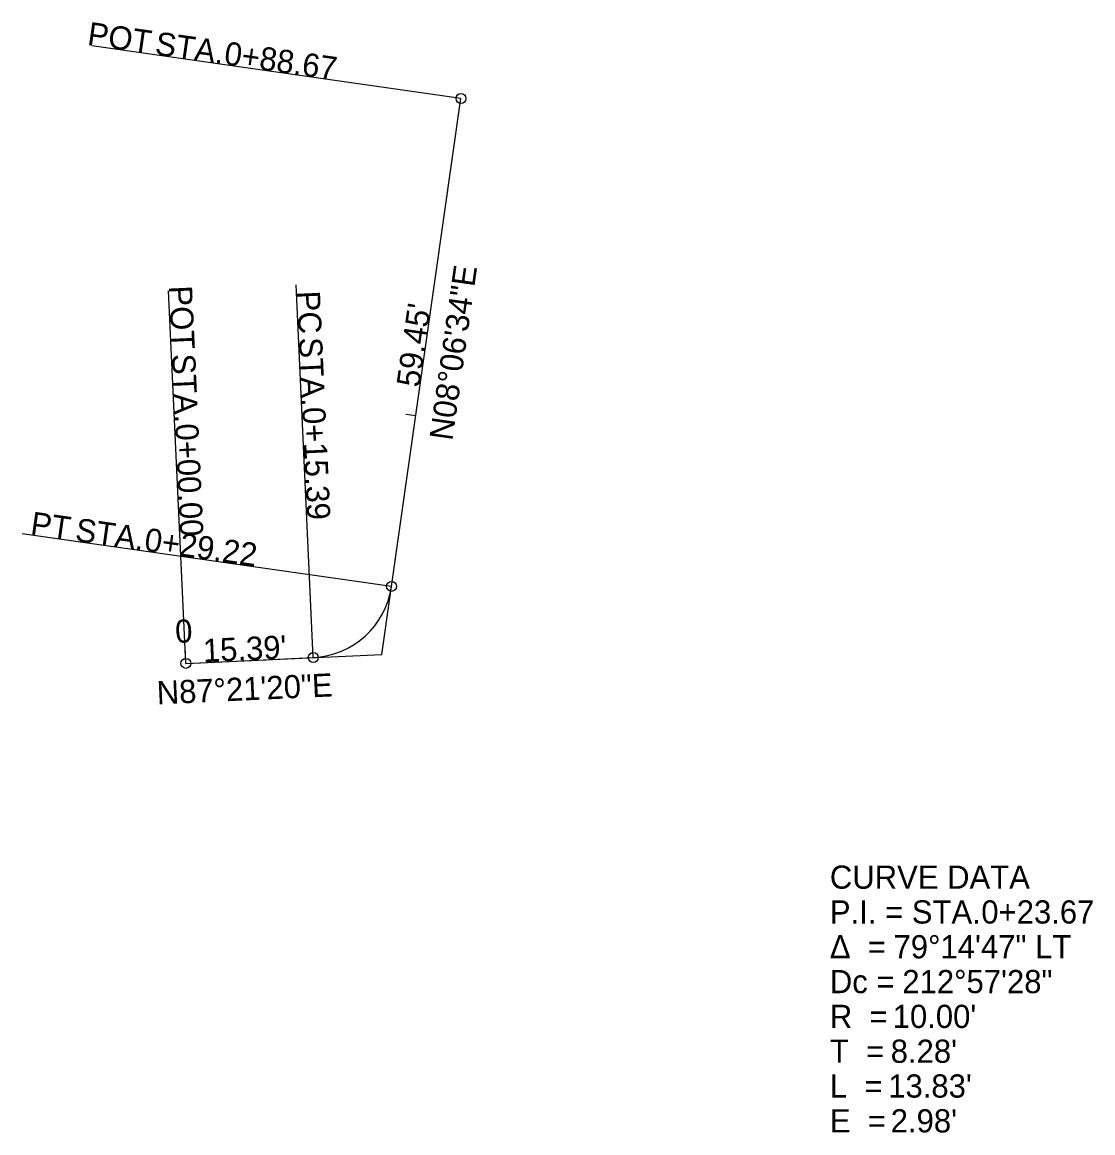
# Model space of a CAD drawing. Extents: x 2047518 to 2047647, y 284910 to 285044.
import ezdxf

# ---------------------------------------------------------------- set-up
doc = ezdxf.new("R2010")
doc.units = 0
for name, color, linetype in [('_CIVIL_CONSTRUCTION', 7, 'Continuous'), ('PF_P_Sta_Elev_Text', 7, 'Continuous'), ('PF_P_Text_Strip_Grades_20', 7, 'Continuous'), ('PF_X_Text_Strip_Grade', 7, 'Continuous'), ('RW_X_CL_100_Distances', 7, 'Continuous'), ('RW_X_Esmt_SH', 7, 'Continuous'), ('SH_Major_Grid_Line', 7, 'Continuous')]:
    doc.layers.add(name, color=color, linetype=linetype)

msp = doc.modelspace()

# ---------------------------------------------------------------- linework, layer by layer
at = {"layer": '_CIVIL_CONSTRUCTION'}
for p, q in [((2047561.59, 284967.64), (2047571.14, 285034.7)), ((2047537.95, 284966.55), (2047561.59, 284967.64))]:
    msp.add_line(p, q, dxfattribs=at)
msp.add_arc((2047552.86, 284977.25), 10, 272.6444, 351.8907, dxfattribs=at)
at = {"layer": 'PF_P_Text_Strip_Grades_20'}
for p, q in [((2047565.69, 284996.41), (2047564.5, 284996.58)), ((2047537.95, 284966.55), (2047537.85, 284968.55))]:
    msp.add_line(p, q, dxfattribs=at)
at = {"layer": 'RW_X_CL_100_Distances'}
for p, q in [((2047562.76, 284975.84), (2047571.14, 285034.7)), ((2047537.95, 284966.55), (2047553.32, 284967.26))]:
    msp.add_line(p, q, dxfattribs=at)
msp.add_arc((2047552.86, 284977.25), 10, 272.6444, 351.8907, dxfattribs=at)
at = {"layer": 'RW_X_Esmt_SH'}
for p, q in [((2047562.76, 284975.84), (2047571.14, 285034.7)), ((2047537.95, 284966.55), (2047553.32, 284967.26))]:
    msp.add_line(p, q, dxfattribs=at)
msp.add_arc((2047552.86, 284977.25), 10, 272.6444, 351.8907, dxfattribs=at)
at = {"layer": 'SH_Major_Grid_Line'}
for p, q in [((2047571.14, 285034.7), (2047526.59, 285041.05)), ((2047537.95, 284966.55), (2047535.87, 285011.5)), ((2047553.32, 284967.26), (2047551.24, 285012.21)), ((2047562.76, 284975.84), (2047518.21, 284982.19))]:
    msp.add_line(p, q, dxfattribs=at)
for centre in [(2047571.14, 285034.7), (2047562.76, 284975.84), (2047537.95, 284966.55), (2047553.32, 284967.26)]:
    msp.add_circle(centre, 0.6, dxfattribs=at)

# ---------------------------------------------------------------- texts
at = {"layer": '_CIVIL_CONSTRUCTION'}
for s, rotation, p in [('N08°06\'34"E', 81.8907, (2047570.1, 284993.34)), ('N87°21\'20"E', 2.6444, (2047534.5, 284961.59))]:
    msp.add_text(s, height=2.8, rotation=rotation, dxfattribs=at).set_placement(p)
at = {"layer": 'PF_P_Sta_Elev_Text'}
for s, p in [('CURVE DATA', (2047615.64, 284939.36)), ('P.I. = STA. ', (2047615.64, 284935.16)), ('0+23.67', (2047633.91, 284935.16)), ('Δ  = ', (2047615.64, 284930.96)), ('79°14\'47" LT', (2047623.32, 284930.96)), ('Dc = ', (2047615.64, 284926.76)), ('212°57\'28"', (2047624.38, 284926.76)), ('R  = ', (2047615.64, 284922.56)), ("10.00'", (2047623.22, 284922.56)), ('T  = ', (2047615.64, 284918.36)), ("8.28'", (2047622.98, 284918.36)), ('L  = ', (2047615.64, 284914.16)), ("13.83'", (2047622.68, 284914.16)), ('E  = ', (2047615.64, 284909.96)), ("2.98'", (2047622.98, 284909.96))]:
    msp.add_text(s, height=2.8, dxfattribs=at).set_placement(p)
at = {"layer": 'PF_P_Text_Strip_Grades_20'}
msp.add_text('0', height=2.8, rotation=2.6444, dxfattribs=at).set_placement((2047536.72, 284969))
at = {"layer": 'PF_X_Text_Strip_Grade'}
for s, rotation, p in [("59.45'", 81.8907, (2047566.12, 284999.77)), ("15.39'", 2.6444, (2047540.07, 284966.69))]:
    msp.add_text(s, height=2.8, rotation=rotation, dxfattribs=at).set_placement(p)
at = {"layer": 'SH_Major_Grid_Line'}
for s, rotation, p in [('POT', 351.8907, (2047525.97, 285041.18)), (' STA. ', 351.8907, (2047533.1, 285040.16)), ('0+88.67', 351.8907, (2047542.46, 285038.83)), ('POT', 272.6444, (2047535.89, 285012.07)), ('PC', 272.6444, (2047551.32, 285011.44)), (' STA. ', 272.6444, (2047551.53, 285006.86)), (' STA. ', 272.6444, (2047536.22, 285004.88)), ('0+15.39', 272.6444, (2047551.97, 284997.42)), ('0+00.00', 272.6444, (2047536.65, 284995.43)), ('PT', 351.8907, (2047519.1, 284982.1)), (' STA. ', 351.8907, (2047523.47, 284981.48)), ('0+29.22', 351.8907, (2047532.83, 284980.15))]:
    msp.add_text(s, height=2.8, rotation=rotation, dxfattribs=at).set_placement(p)

doc.saveas('drawing.dxf')
